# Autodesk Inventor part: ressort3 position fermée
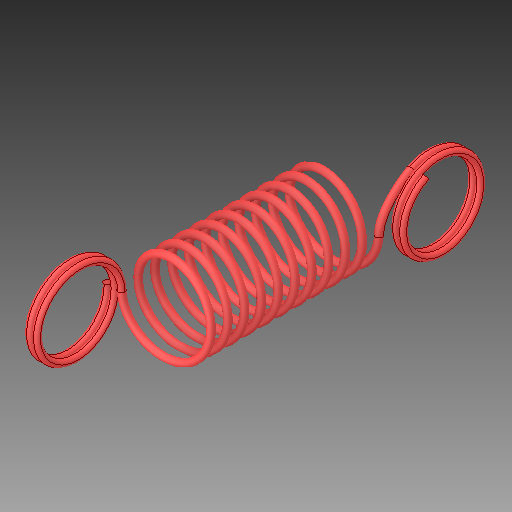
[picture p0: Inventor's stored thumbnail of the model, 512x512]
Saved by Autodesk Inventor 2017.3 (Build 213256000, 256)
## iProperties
Created: 2007-12
Part Number: ressort3 position fermée
Material: Générique
Document SubType Name: Modeling
Designer: ficho
Density: 1 g/cm^3
Appearance: Par défaut
Author: ficho
Sending System: SolidWorks 2009
Last Author: christophe
Last Saved: 2011-02-10
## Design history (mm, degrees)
feature "Lissage1"
node "Solide1"
